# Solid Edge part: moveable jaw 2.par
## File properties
Author: CADSoft
Template: Normal.par
Last saved by: CADCIM
Revision: 6
Application: Solid Edge
Accuracy: 0.990
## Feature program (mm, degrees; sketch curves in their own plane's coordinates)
sketch for "unnamed Protrusion 1" plane through (0, 0, 0) normal (0, -1, 0) x-axis (1, 0, 0)
  line (2.077, -7.5) -> (2.077, 52.5)
  line (2.077, 52.5) -> (-32.423, 52.5)
  line (-32.423, 52.5) -> (-32.423, -7.5)
  line (-28.923, -7.5) -> (-32.423, -7.5)
  line (-28.923, -5) -> (-28.923, -7.5)
  line (-28.923, -5) -> (-26.423, -5)
  line (-26.423, -5) -> (-26.423, -2.5)
  line (-26.423, -2.5) -> (-23.923, -2.5)
  line (-23.923, -2.5) -> (-23.923, 0)
  line (-23.923, 0) -> (-21.423, 0)
  line (-21.423, 0) -> (-21.423, 2.5)
  line (-21.423, 2.5) -> (-18.923, 2.5)
  line (-18.923, 2.5) -> (-18.923, 5)
  line (-18.923, 5) -> (-16.423, 5)
  line (-16.423, 5) -> (-16.423, 7.5)
  line (-16.423, 7.5) -> (-15.173, 7.5)
  line (-13.923, 7.5) -> (-15.173, 7.5)
  line (-13.923, 5) -> (-13.923, 7.5)
  line (-11.423, 5) -> (-13.923, 5)
  line (-11.423, 2.5) -> (-11.423, 5)
  line (-8.923, 2.5) -> (-11.423, 2.5)
  line (-8.923, 0) -> (-8.923, 2.5)
  line (-6.423, 0) -> (-8.923, 0)
  line (-6.423, -2.5) -> (-6.423, 0)
  line (-3.923, -2.5) -> (-6.423, -2.5)
  line (-3.923, -5) -> (-3.923, -2.5)
  line (-1.423, -5) -> (-3.923, -5)
  line (-1.423, -5) -> (-1.423, -7.5)
  line (-1.423, -7.5) -> (2.077, -7.5)
extrude "unnamed Protrusion 1" add finite 18 symmetric
sketch for "Hole_1" plane through (-15.173, 0, 52.5) normal (0, 0, 1) x-axis (-1, 0, 0)
  hole centre (0, 0) bore radius 6
hole "Hole_1" diameter 12 finite  VBottomAngle = 120 deg
sketch for "Hole_2" plane through (2.077, 0, 22.5) normal (1, 0, 0) x-axis (0, 1, 0)
  hole centre (0, 23) bore radius 3
hole "Hole_2" diameter 6 through
chamfer "Chamfer_2" setback 2
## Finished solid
Body 1: solid body, 38 faces, 98 edges, 60 vertices.
  Faces by surface: plane 34, cylinder 3, cone 1
  Edges by curve: line 92, circle 4, intersection 2
Bounding box of the edges (mm): 34.500 x 18.000 x 60.000, from (-32.423, -9, -7.5) to (2.077, 9, 52.5).
Cylindrical faces by radius (mm): R3 x2, R6 x1
Conical faces (half-angle, radius in mm at the cone's reference point): 60 deg R6 x1
Planar faces by outward normal: +x 7, +y 1, +z 1, -x 7, -y 1, -z 13, oblique 4
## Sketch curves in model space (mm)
line (-26.423, 0, -5) -> (-26.423, 0, -2.5)
line (-26.423, 0, -2.5) -> (-23.923, 0, -2.5)
line (-23.923, 0, -2.5) -> (-23.923, 0, 0)
line (-23.923, 0, 0) -> (-21.423, 0, 0)
line (-21.423, 0, 0) -> (-21.423, 0, 2.5)
line (-21.423, 0, 2.5) -> (-18.923, 0, 2.5)
line (-18.923, 0, 2.5) -> (-18.923, 0, 5)
line (-18.923, 0, 5) -> (-16.423, 0, 5)
line (-16.423, 0, 5) -> (-16.423, 0, 7.5)
line (-16.423, 0, 7.5) -> (-15.173, 0, 7.5)
line (-13.923, 0, 7.5) -> (-15.173, 0, 7.5)
line (-13.923, 0, 5) -> (-13.923, 0, 7.5)
line (-11.423, 0, 5) -> (-13.923, 0, 5)
line (-11.423, 0, 2.5) -> (-11.423, 0, 5)
line (-8.923, 0, 2.5) -> (-11.423, 0, 2.5)
line (-8.923, 0, 0) -> (-8.923, 0, 2.5)
line (-6.423, 0, 0) -> (-8.923, 0, 0)
line (-6.423, 0, -2.5) -> (-6.423, 0, 0)
line (-3.923, 0, -2.5) -> (-6.423, 0, -2.5)
line (-3.923, 0, -5) -> (-3.923, 0, -2.5)
line (-1.423, 0, -5) -> (-3.923, 0, -5)
line (-1.423, 0, -5) -> (-1.423, 0, -7.5)
line (-1.423, 0, -7.5) -> (2.077, 0, -7.5)
line (2.077, 0, -7.5) -> (2.077, 0, 52.5)
line (2.077, 0, 52.5) -> (-32.423, 0, 52.5)
line (-32.423, 0, 52.5) -> (-32.423, 0, -7.5)
line (-28.923, 0, -7.5) -> (-32.423, 0, -7.5)
line (-28.923, 0, -5) -> (-28.923, 0, -7.5)
line (-28.923, 0, -5) -> (-26.423, 0, -5)
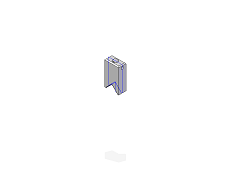
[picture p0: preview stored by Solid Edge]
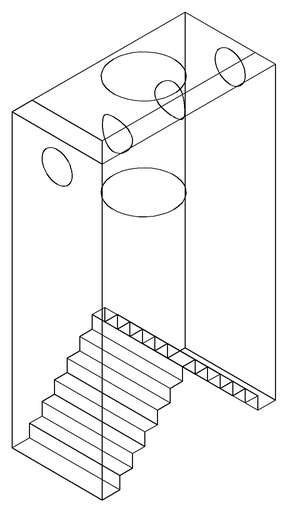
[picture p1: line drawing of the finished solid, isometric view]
